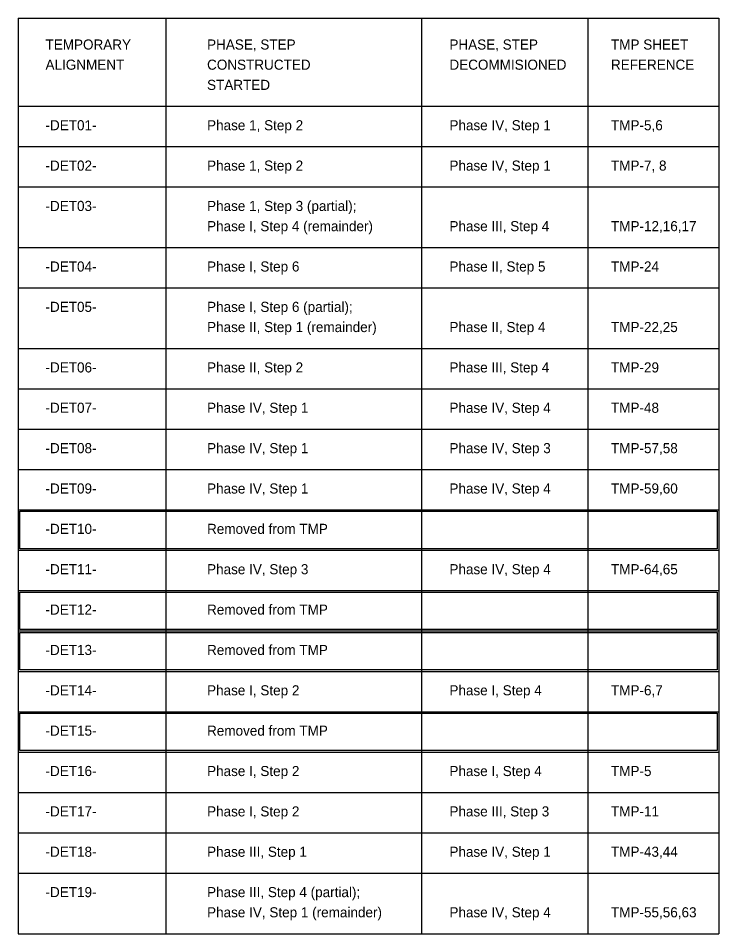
# Model space of a CAD drawing. Extents: x 2495290 to 2495776, y 371142 to 371777.
import ezdxf

# ---------------------------------------------------------------- set-up
doc = ezdxf.new("R2010")
doc.units = 0
for name, color, linetype in [('TC CONSTRUCTION PROPOSED ROADWAY SHADE', 7, 'Continuous'), ('TC LABEL TEXT', 7, 'Continuous'), ('TC SHEET BORDER LINE THIN', 7, 'Continuous')]:
    doc.layers.add(name, color=color, linetype=linetype)

msp = doc.modelspace()

# ---------------------------------------------------------------- linework, layer by layer
at = {"layer": 'TC CONSTRUCTION PROPOSED ROADWAY SHADE'}
for points in [[(2495291.44, 371434.71), (2495774.93, 371434.71), (2495774.93, 371408.71), (2495291.44, 371408.71)], [(2495291.44, 371378.71), (2495774.93, 371378.71), (2495774.93, 371352.71), (2495291.44, 371352.71)], [(2495291.44, 371350.71), (2495774.93, 371350.71), (2495774.93, 371324.71), (2495291.44, 371324.71)], [(2495291.44, 371294.71), (2495774.93, 371294.71), (2495774.93, 371268.71), (2495291.44, 371268.71)]]:
    msp.add_lwpolyline(points, close=True, dxfattribs=at)
at = {"layer": 'TC LABEL TEXT'}
for p, q in [((2495290.44, 371776.73), (2495290.44, 371141.71)), ((2495290.44, 371776.73), (2495775.93, 371776.73)), ((2495392.68, 371776.73), (2495392.68, 371141.71)), ((2495570.02, 371776.73), (2495570.02, 371141.71)), ((2495685.22, 371776.73), (2495685.22, 371141.71)), ((2495775.93, 371776.73), (2495775.93, 371141.71)), ((2495290.44, 371715.71), (2495775.93, 371715.71)), ((2495290.44, 371687.71), (2495775.93, 371687.71)), ((2495290.44, 371659.71), (2495775.93, 371659.71)), ((2495290.44, 371617.71), (2495775.93, 371617.71)), ((2495290.44, 371589.71), (2495775.93, 371589.71)), ((2495290.44, 371547.71), (2495775.93, 371547.71)), ((2495290.44, 371519.71), (2495775.93, 371519.71)), ((2495290.44, 371491.71), (2495775.93, 371491.71)), ((2495290.44, 371463.71), (2495775.93, 371463.71)), ((2495290.44, 371435.71), (2495775.93, 371435.71)), ((2495290.44, 371407.71), (2495775.93, 371407.71)), ((2495290.44, 371379.71), (2495775.93, 371379.71)), ((2495290.44, 371351.71), (2495775.93, 371351.71)), ((2495290.44, 371323.71), (2495775.93, 371323.71)), ((2495290.44, 371295.71), (2495775.93, 371295.71)), ((2495290.44, 371267.71), (2495775.93, 371267.71)), ((2495290.44, 371239.71), (2495775.93, 371239.71)), ((2495290.44, 371211.71), (2495775.93, 371211.71)), ((2495290.44, 371183.71), (2495775.93, 371183.71)), ((2495290.44, 371141.71), (2495775.93, 371141.71))]:
    msp.add_line(p, q, dxfattribs=at)

# ---------------------------------------------------------------- texts
at = {"layer": 'TC SHEET BORDER LINE THIN'}
for s, p in [('TEMPORARY', (2495309.28, 371755.06)), ('PHASE, STEP', (2495421.28, 371755.06)), ('PHASE, STEP ', (2495589.28, 371755.06)), ('TMP SHEET', (2495701.28, 371755.06)), ('ALIGNMENT', (2495309.28, 371741.06)), ('CONSTRUCTED', (2495421.28, 371741.06)), ('DECOMMISIONED', (2495589.28, 371741.06)), ('REFERENCE', (2495701.28, 371741.06)), ('STARTED', (2495421.28, 371727.06)), ('-DET01-', (2495309.28, 371699.06)), ('Phase 1, Step 2', (2495421.28, 371699.06)), ('Phase IV, Step 1', (2495589.28, 371699.06)), ('TMP-5,6', (2495701.28, 371699.06)), ('-DET02-', (2495309.28, 371671.06)), ('Phase 1, Step 2', (2495421.28, 371671.06)), ('Phase IV, Step 1', (2495589.28, 371671.06)), ('TMP-7, 8', (2495701.28, 371671.06)), ('-DET03-', (2495309.28, 371643.06)), ('Phase 1, Step 3 (partial); ', (2495421.28, 371643.06)), ('Phase I, Step 4 (remainder)', (2495421.28, 371629.06)), ('Phase III, Step 4', (2495589.28, 371629.06)), ('TMP-12,16,17', (2495701.28, 371629.06)), ('-DET04-', (2495309.28, 371601.06)), ('Phase I, Step 6', (2495421.28, 371601.06)), ('Phase II, Step 5', (2495589.28, 371601.06)), ('TMP-24', (2495701.28, 371601.06)), ('-DET05-', (2495309.28, 371573.06)), ('Phase I, Step 6 (partial); ', (2495421.28, 371573.06)), ('Phase II, Step 1 (remainder)', (2495421.28, 371559.06)), ('Phase II, Step 4', (2495589.28, 371559.06)), ('TMP-22,25', (2495701.28, 371559.06)), ('-DET06-', (2495309.28, 371531.06)), ('Phase II, Step 2', (2495421.28, 371531.06)), ('Phase III, Step 4', (2495589.28, 371531.06)), ('TMP-29', (2495701.28, 371531.06)), ('Phase IV, Step 1', (2495421.28, 371503.06)), ('Phase IV, Step 4', (2495589.28, 371503.06)), ('-DET07-', (2495309.28, 371503.06)), ('TMP-48', (2495701.28, 371503.06)), ('-DET08-', (2495309.28, 371475.06)), ('Phase IV, Step 1', (2495421.28, 371475.06)), ('Phase IV, Step 3', (2495589.28, 371475.06)), ('TMP-57,58', (2495701.28, 371475.06)), ('-DET09-', (2495309.28, 371447.06)), ('Phase IV, Step 1', (2495421.28, 371447.06)), ('Phase IV, Step 4', (2495589.28, 371447.06)), ('TMP-59,60', (2495701.28, 371447.06)), ('-DET10-', (2495309.28, 371419.06)), ('Removed from TMP', (2495421.28, 371419.06)), ('-DET11-', (2495309.28, 371391.06)), ('Phase IV, Step 3', (2495421.28, 371391.06)), ('Phase IV, Step 4', (2495589.28, 371391.06)), ('TMP-64,65', (2495701.28, 371391.06)), ('-DET12-', (2495309.28, 371363.06)), ('Removed from TMP', (2495421.28, 371363.06)), ('-DET13-', (2495309.28, 371335.06)), ('Removed from TMP', (2495421.28, 371335.06)), ('-DET14-', (2495309.28, 371307.06)), ('Phase I, Step 2', (2495421.28, 371307.06)), ('Phase I, Step 4', (2495589.28, 371307.06)), ('TMP-6,7', (2495701.28, 371307.06)), ('-DET15-', (2495309.28, 371279.06)), ('Removed from TMP', (2495421.28, 371279.06)), ('-DET16-', (2495309.28, 371251.06)), ('Phase I, Step 2', (2495421.28, 371251.06)), ('Phase I, Step 4', (2495589.28, 371251.06)), ('TMP-5', (2495701.28, 371251.06)), ('-DET17-', (2495309.28, 371223.06)), ('Phase I, Step 2', (2495421.28, 371223.06)), ('Phase III, Step 3', (2495589.28, 371223.06)), ('TMP-11', (2495701.28, 371223.06)), ('-DET18-', (2495309.28, 371195.06)), ('Phase III, Step 1', (2495421.28, 371195.06)), ('Phase IV, Step 1', (2495589.28, 371195.06)), ('TMP-43,44', (2495701.28, 371195.06)), ('-DET19-', (2495309.28, 371167.06)), ('Phase III, Step 4 (partial);', (2495421.28, 371167.06)), ('Phase IV, Step 1 (remainder)', (2495421.28, 371153.06)), ('Phase IV, Step 4', (2495589.28, 371153.06)), ('TMP-55,56,63', (2495701.28, 371153.06))]:
    msp.add_text(s, height=7, dxfattribs=at).set_placement(p)

doc.saveas('drawing.dxf')
